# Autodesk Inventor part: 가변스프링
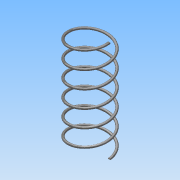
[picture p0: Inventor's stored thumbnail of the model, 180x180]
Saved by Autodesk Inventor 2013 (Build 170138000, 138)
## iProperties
Created: 2016-11
Part Number: 가변스프링
Material: 강철, 탄소
Document SubType Name: Modeling
Designer: Administrator
Mass: -0.0411706 g
Surface Area: 38.0676 cm^2
Volume: -0.00523134 cm^3
Density: 7.87 g/cm^3
Author: Administrator
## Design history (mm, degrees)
sketch "스케치1"
  geometry: L1 (0, 0)-(16, 0); L2 (16, 0)-(16, 84.368); L3 (16, 84.368)-(0, 84.368); L4 (0, 84.368)-(0, 0); C1 r 1 at (16, 0)
  constraints: 8 end point, 2 parallel, 1 centre point, 1 coincident, 1 horizontal, 1 perpendicular
  dimensions: "d0" = 32 diameter of L2 L4; "d2" = 84.36759 distance of L1.end L2.end (derived); "d3" = 2 diameter of C1
feature "코일1" sketch "스케치1" pitch "d4" = 10; turns "d6" = 6; dims "d5" = 84.36759 (= d2), "d7" = 0, angle "d8" = 90 deg, angle "d9" = 90 deg, "d10" = 0, "d11" = 0
node "작업 평면1"
feature "분할1"
feature "분할2"
node "솔리드1"
other parameters: "d12" = 85
